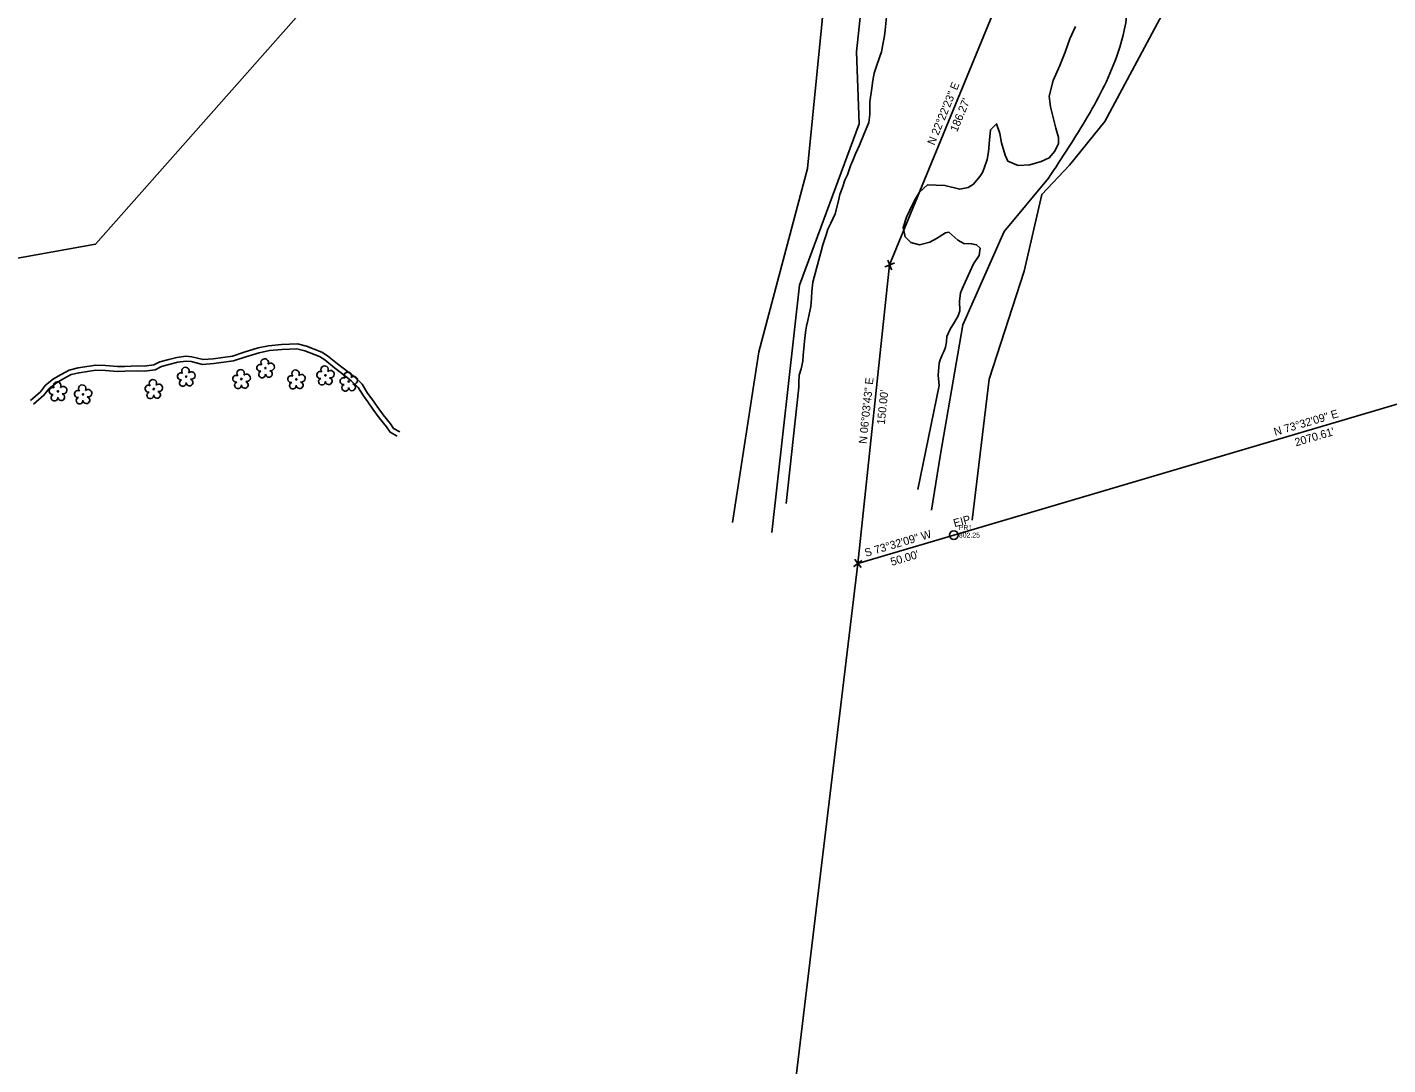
# Model space of a CAD drawing. Extents: x 1316460 to 1321645, y 684173 to 687077.
# Drawn here: x 1319196 to 1319876, y 684734 to 685253 of the extents above; entities that cross this region are included whole.
import ezdxf

# ---------------------------------------------------------------- set-up
doc = ezdxf.new("R2010")
doc.units = 0
for name, color, linetype in [('Exist Hydro Stream or Body of Water', 7, 'Continuous'), ('Exist Hydrographic Confluence CELL', 7, 'Continuous'), ('Exist Hydrographic Confluence Cogo Description', 7, 'Continuous'), ('Exist Hydrographic Confluence Cogo Elevation', 7, 'Continuous'), ('Exist Hydrographic Confluence Cogo Number', 7, 'Continuous'), ('Exist Hydrographic Water Edge Cogo Elevation', 7, 'Continuous'), ('Exist Property Corner CELL', 7, 'Continuous'), ('Exist Property Iron Pin Text', 7, 'Continuous'), ('Exist Property Line', 7, 'Continuous'), ('Exist Property Line Text', 7, 'Continuous'), ('Exist Vegetation Woods Line', 7, 'Continuous'), ('Old_Level_59', 7, 'Continuous')]:
    doc.layers.add(name, color=color, linetype=linetype)

msp = doc.modelspace()

# ---------------------------------------------------------------- linework, layer by layer
at = {"layer": 'Exist Hydro Stream or Body of Water'}
for points in [[(1319197.78, 685066.37), (1319202.79, 685070.76), (1319205.37, 685074.09), (1319209.41, 685077.27), (1319213.24, 685079.48), (1319217.21, 685081.63), (1319221.67, 685082.69), (1319230.45, 685084.03), (1319235.43, 685083.85), (1319241.37, 685083.37), (1319244.92, 685083.46), (1319251.52, 685083.73), (1319254.74, 685083.54), (1319259.51, 685084.18), (1319262.51, 685085.72), (1319267.01, 685086.96), (1319271.04, 685087.95), (1319275.55, 685088.51), (1319278.5, 685088.3), (1319284.12, 685086.82), (1319289.2, 685087.3), (1319298.82, 685088.64), (1319304.76, 685090.51), (1319311.64, 685092.65), (1319316.91, 685093.79), (1319323.41, 685094.31), (1319331.32, 685094.65), (1319335.78, 685093.6), (1319343.51, 685090.57), (1319346.4, 685088.7), (1319351.4, 685084.71), (1319357.06, 685080.37), (1319359.83, 685078.17), (1319363.67, 685074.49), (1319366.29, 685070.08), (1319368.57, 685067.27), (1319371.12, 685063.4), (1319374.17, 685059.19), (1319377.78, 685054.7), (1319379.36, 685052.41), (1319382.43, 685050.69)], [(1319197.78, 685066.37), (1319202.79, 685070.76), (1319205.37, 685074.09), (1319209.41, 685077.27), (1319213.24, 685079.48), (1319217.21, 685081.63), (1319221.67, 685082.69), (1319230.45, 685084.03), (1319235.43, 685083.85), (1319241.37, 685083.37), (1319244.92, 685083.46), (1319251.52, 685083.73), (1319254.74, 685083.54), (1319259.51, 685084.18), (1319262.51, 685085.72), (1319267.01, 685086.96), (1319271.04, 685087.95), (1319275.55, 685088.51), (1319278.5, 685088.3), (1319284.12, 685086.82), (1319289.2, 685087.3), (1319298.82, 685088.64), (1319304.76, 685090.51), (1319311.64, 685092.65), (1319316.91, 685093.79), (1319323.41, 685094.31), (1319331.32, 685094.65), (1319335.78, 685093.6), (1319343.51, 685090.57), (1319346.4, 685088.7), (1319351.4, 685084.71), (1319357.06, 685080.37), (1319359.83, 685078.17), (1319363.67, 685074.49), (1319366.29, 685070.08), (1319368.57, 685067.27), (1319371.12, 685063.4), (1319374.17, 685059.19), (1319377.78, 685054.7), (1319379.36, 685052.41), (1319382.43, 685050.69)], [(1319199.4, 685064.52), (1319204.59, 685069.06), (1319207.13, 685072.34), (1319210.79, 685075.23), (1319214.44, 685077.34), (1319218.1, 685079.32), (1319222.14, 685080.28), (1319230.59, 685081.57), (1319235.28, 685081.39), (1319241.3, 685080.91), (1319245, 685081), (1319251.5, 685081.26), (1319254.83, 685081.07), (1319260.25, 685081.79), (1319263.41, 685083.41), (1319267.63, 685084.58), (1319271.48, 685085.53), (1319275.62, 685086.04), (1319278.1, 685085.86), (1319283.92, 685084.33), (1319289.49, 685084.86), (1319299.36, 685086.23), (1319305.49, 685088.17), (1319312.26, 685090.27), (1319317.28, 685091.35), (1319323.56, 685091.86), (1319331.09, 685092.18), (1319335.05, 685091.25), (1319342.38, 685088.37), (1319344.96, 685086.7), (1319349.88, 685082.77), (1319355.54, 685078.43), (1319358.21, 685076.31), (1319361.73, 685072.94), (1319364.27, 685068.67), (1319366.59, 685065.82), (1319369.09, 685062), (1319372.22, 685057.69), (1319375.81, 685053.22), (1319377.66, 685050.54), (1319381.23, 685048.54)]]:
    msp.add_lwpolyline(points, dxfattribs=at)
at = {"layer": 'Exist Hydrographic Confluence CELL'}
for radius in [2.2, 2.2, 0.0707, 0.0707]:
    msp.add_circle((1319659.5, 684999.15), radius, dxfattribs=at)
at = {"layer": 'Exist Hydrographic Confluence Cogo Description'}
for p, q in [((1319315.33, 685082.58), (1319315.33, 685082.58)), ((1319275.69, 685078.3), (1319275.69, 685078.3)), ((1319303.32, 685077.12), (1319303.32, 685077.12)), ((1319330.76, 685076.95), (1319330.76, 685076.95)), ((1319345.29, 685078.98), (1319345.29, 685078.98)), ((1319356.95, 685075.91), (1319356.95, 685075.91)), ((1319211.57, 685070.98), (1319211.57, 685070.98)), ((1319224.1, 685069.47), (1319224.1, 685069.47)), ((1319259.47, 685072.12), (1319259.47, 685072.12))]:
    msp.add_line(p, q, dxfattribs=at)
for centre in [(1319315.33, 685082.58), (1319275.69, 685078.3), (1319303.32, 685077.12), (1319330.76, 685076.95), (1319345.29, 685078.98), (1319356.95, 685075.91), (1319211.57, 685070.98), (1319224.1, 685069.47), (1319259.47, 685072.12)]:
    msp.add_circle(centre, 0.326, dxfattribs=at)
for centre, radius, start, end in [((1319275.31, 685081.17), 1.86, 330.16508, 219.71335), ((1319302.93, 685079.99), 1.86, 330.16508, 219.71335), ((1319312.73, 685082.73), 1.73, 62.66361, 279.3457), ((1319314.95, 685085.45), 1.86, 330.16508, 219.71335), ((1319317.88, 685083.16), 1.9, 257.1011, 134.19993), ((1319344.91, 685081.85), 1.86, 330.16508, 219.71335), ((1319211.19, 685073.86), 1.86, 330.16508, 219.71335), ((1319259.08, 685075), 1.86, 330.16508, 219.71335), ((1319273.09, 685078.45), 1.73, 62.66361, 279.3457), ((1319273.99, 685075.18), 1.69, 111.56708, 6.23104), ((1319277.37, 685075.4), 1.7, 181.28216, 74.55999), ((1319278.24, 685078.89), 1.9, 257.1011, 134.19993), ((1319300.71, 685077.27), 1.73, 62.66361, 279.3457), ((1319301.61, 685074), 1.69, 111.56708, 6.23104), ((1319304.99, 685074.22), 1.7, 181.28216, 74.55999), ((1319305.87, 685077.71), 1.9, 257.1011, 134.19993), ((1319313.63, 685079.45), 1.69, 111.56708, 6.23104), ((1319317, 685079.68), 1.7, 181.28216, 74.55999), ((1319328.15, 685077.1), 1.73, 62.66361, 279.3457), ((1319329.06, 685073.83), 1.69, 111.56708, 6.23104), ((1319330.37, 685079.82), 1.86, 330.16508, 219.71335), ((1319332.43, 685074.05), 1.7, 181.28216, 74.55999), ((1319333.31, 685077.53), 1.9, 257.1011, 134.19993), ((1319342.69, 685079.13), 1.73, 62.66361, 279.3457), ((1319343.59, 685075.86), 1.69, 111.56708, 6.23104), ((1319346.96, 685076.08), 1.7, 181.28216, 74.55999), ((1319347.84, 685079.57), 1.9, 257.1011, 134.19993), ((1319354.34, 685076.07), 1.73, 62.66361, 279.3457), ((1319356.56, 685078.79), 1.86, 330.16508, 219.71335), ((1319359.5, 685076.5), 1.9, 257.1011, 134.19993), ((1319208.96, 685071.14), 1.73, 62.66361, 279.3457), ((1319209.87, 685067.86), 1.69, 111.56708, 6.23104), ((1319213.24, 685068.08), 1.7, 181.28216, 74.55999), ((1319214.12, 685071.57), 1.9, 257.1011, 134.19993), ((1319221.49, 685069.62), 1.73, 62.66361, 279.3457), ((1319223.71, 685072.34), 1.86, 330.16508, 219.71335), ((1319225.77, 685066.57), 1.7, 181.28216, 74.55999), ((1319226.65, 685070.06), 1.9, 257.1011, 134.19993), ((1319256.86, 685072.28), 1.73, 62.66361, 279.3457), ((1319257.76, 685069), 1.69, 111.56708, 6.23104), ((1319261.14, 685069.23), 1.7, 181.28216, 74.55999), ((1319262.02, 685072.71), 1.9, 257.1011, 134.19993), ((1319355.24, 685072.79), 1.69, 111.56708, 6.23104), ((1319358.62, 685073.01), 1.7, 181.28216, 74.55999), ((1319222.39, 685066.35), 1.69, 111.56708, 6.23104)]:
    msp.add_arc(centre, radius, start, end, dxfattribs=at)
at = {"layer": 'Exist Hydrographic Water Edge Cogo Elevation'}
for points in [[(1319582.01, 685072.99), (1319581.93, 685075.46), (1319582.23, 685079.12), (1319583.15, 685082.17), (1319583.95, 685086.12), (1319584.11, 685088.86), (1319584.64, 685094.17), (1319585.07, 685097.77), (1319585.43, 685101.51), (1319585.83, 685103.55), (1319586.44, 685106.45), (1319588.04, 685113.31), (1319588.38, 685117.37), (1319588.49, 685121.02), (1319589, 685125.54), (1319593.14, 685140.96), (1319593.99, 685144.13), (1319595.64, 685149.18), (1319596.51, 685152.09), (1319597.96, 685154.98), (1319599.11, 685157.46), (1319600.15, 685159.67), (1319601.62, 685165.48), (1319602.43, 685169.37), (1319603.78, 685172.9), (1319605, 685176.43), (1319606.32, 685179.24), (1319607.82, 685183.62), (1319609.08, 685186.37), (1319610.38, 685189.7), (1319612.34, 685193.92), (1319614.89, 685200.13), (1319616.99, 685205.33), (1319617.53, 685209.27), (1319617.54, 685215.58), (1319618.43, 685222.47), (1319619.04, 685226.28), (1319619.73, 685229.97), (1319621.15, 685234.48), (1319623.25, 685240.66), (1319624.08, 685244.22), (1319624.79, 685248.56), (1319625.14, 685251.51), (1319625.94, 685259.76)], [(1319652.19, 685073.83), (1319651.68, 685079.08), (1319652.09, 685085.09), (1319652.58, 685086.74), (1319653.84, 685089.55), (1319654.58, 685091.29), (1319655.26, 685093.02), (1319655.75, 685095.66), (1319655.97, 685098.47), (1319657.58, 685102.08), (1319659.78, 685105.53), (1319661.74, 685108.64), (1319662.42, 685111.29), (1319662.27, 685116.03), (1319662.8, 685120.16), (1319664.41, 685123.65), (1319669.28, 685134.74), (1319672.21, 685138.89), (1319672.58, 685142.49), (1319670.85, 685144.27), (1319668.41, 685144.71), (1319664.57, 685144.81), (1319661.53, 685146.58), (1319657.07, 685150.47), (1319655.26, 685150.23), (1319650.88, 685147.37), (1319647.47, 685145.6), (1319642.29, 685144.11), (1319638.04, 685145.42), (1319635.14, 685148.24), (1319634.15, 685152.8), (1319635.79, 685157.98), (1319637.46, 685161.59), (1319639.91, 685166.29), (1319642.32, 685170.54), (1319646.27, 685174.1), (1319655.07, 685173.91), (1319662.48, 685171.95), (1319666.58, 685172.91), (1319669.29, 685174.44), (1319672.5, 685178.41), (1319673.75, 685180.38), (1319674.6, 685182.51), (1319676.09, 685186.9), (1319676.83, 685190.71), (1319677.27, 685196.47), (1319677.87, 685201.58), (1319680.81, 685204.69), (1319682.53, 685199.84), (1319683.34, 685195.08), (1319685.08, 685188.93), (1319686.49, 685185.96), (1319691.7, 685183.8), (1319697.47, 685184.21), (1319703.1, 685185.86), (1319707.22, 685187.67), (1319710.01, 685190.96), (1319711.86, 685194.84), (1319711.87, 685197.9), (1319710.48, 685202.57), (1319707.9, 685213.09), (1319707.18, 685218.45), (1319709.11, 685226.37), (1319712.51, 685233.8), (1319715.1, 685240.47), (1319717.43, 685247.05), (1319720.25, 685253.21)], [(1319575.7, 685014.97), (1319582.01, 685072.99)], [(1319641.47, 685022), (1319652.19, 685073.83)]]:
    msp.add_lwpolyline(points, dxfattribs=at)
at = {"layer": 'Exist Property Corner CELL'}
for p, q in [((1319627.39, 685134.14), (1319627.39, 685134.14)), ((1319611.55, 684984.98), (1319611.55, 684984.98))]:
    msp.add_line(p, q, dxfattribs=at)
for points in [[(1319626.43, 685136.45), (1319628.35, 685131.83), (1319627.39, 685134.14), (1319629.7, 685135.1), (1319625.08, 685133.18)], [(1319613.09, 684983.01), (1319610.01, 684986.95), (1319611.55, 684984.98), (1319609.58, 684983.44), (1319613.52, 684986.52)]]:
    msp.add_lwpolyline(points, dxfattribs=at)
at = {"layer": 'Exist Property Line'}
for p, q in [((1319659.5, 684999.15), (1321645.21, 685586)), ((1319627.39, 685134.14), (1319698.29, 685306.39)), ((1319611.55, 684984.98), (1319627.39, 685134.14)), ((1319659.5, 684999.15), (1319611.55, 684984.98)), ((1319611.55, 684984.98), (1319573.85, 684672.39))]:
    msp.add_line(p, q, dxfattribs=at)
at = {"layer": 'Exist Vegetation Woods Line'}
for points in [[(1319702.98, 685464.55), (1319717.48, 685430.06), (1319730.9, 685382.44), (1319756.41, 685341.4), (1319764.33, 685313.27), (1319764.8, 685261.4), (1319735.04, 685205.79), (1319717.26, 685184.04), (1319703.45, 685169.39), (1319694.67, 685130.99), (1319677.19, 685077.05), (1319668.6, 685006.56)], [(1319607.35, 685407.56), (1319613.9, 685384.3), (1319620.12, 685328.26), (1319610.86, 685240.62), (1319612.24, 685204.61), (1319582.41, 685124.11), (1319568.55, 685000.4)], [(1319548.79, 685005.46), (1319561.96, 685090.73), (1319586.3, 685182.39), (1319593.67, 685256.2), (1319604, 685376.48), (1319586.79, 685395.44)], [(1319648.36, 685011.58), (1319652.73, 685038.51), (1319663.94, 685104.29), (1319684.71, 685150.79), (1319706.8, 685177.5)]]:
    msp.add_lwpolyline(points, dxfattribs=at)
msp.add_spline([(1319706.8, 685177.5), (1319726.52, 685208.51), (1319741.5, 685239.96), (1319746.45, 685264.47), (1319740.94, 685299.58), (1319724.8, 685338.47)], degree=3, dxfattribs=at)
at = {"layer": 'Old_Level_59'}
msp.add_lwpolyline([(1318697.3, 685264.68), (1318675.61, 685496.37), (1319013.72, 685603.72), (1319178.5, 686302.95), (1319290.7, 686462.26), (1319434.76, 686395.34), (1319426.96, 685366.75), (1319230.41, 685144.48), (1318730.33, 685054.78)], close=True, dxfattribs=at)

# ---------------------------------------------------------------- texts
at = {"layer": 'Exist Hydrographic Confluence Cogo Elevation'}
msp.add_text('802.25', height=2.5, dxfattribs=at).set_placement((1319662, 684997.9))
msp.add_text('802.25', height=2.5, dxfattribs=at).set_placement((1319662, 684997.9))
at = {"layer": 'Exist Hydrographic Confluence Cogo Number'}
msp.add_text('PR1', height=2.5, dxfattribs=at).set_placement((1319662, 685001.65))
msp.add_text('PR1', height=2.5, dxfattribs=at).set_placement((1319662, 685001.65))
at = {"layer": 'Exist Property Iron Pin Text'}
msp.add_text('EIP', height=4, rotation=14.96218, dxfattribs=at).set_placement((1319659.86, 685003.07))
at = {"layer": 'Exist Property Line Text'}
for s, rotation, p in [('N 22%%D22\'23" E', 67.62688, (1319649.73, 685193.68)), ("186.27'", 67.62688, (1319661.12, 685200.32)), ('N 06%%D03\'43" E', 83.93799, (1319615.87, 685044.59)), ("150.00'", 83.93799, (1319624.93, 685054.19)), ('N 73%%D32\'09" E', 16.46417, (1319820.16, 685048.72)), ("2070.61'", 16.46417, (1319830.6, 685043.46)), ('S 73%%D32\'09" W', 16.46429, (1319615.53, 684988.24)), ("50.00'", 16.46429, (1319628.52, 684983.74))]:
    msp.add_text(s, height=4, rotation=rotation, dxfattribs=at).set_placement(p)

doc.saveas('drawing.dxf')
